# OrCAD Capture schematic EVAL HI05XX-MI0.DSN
size A; title: EVAL HI05XX-MI0; rev: A0; note: 1
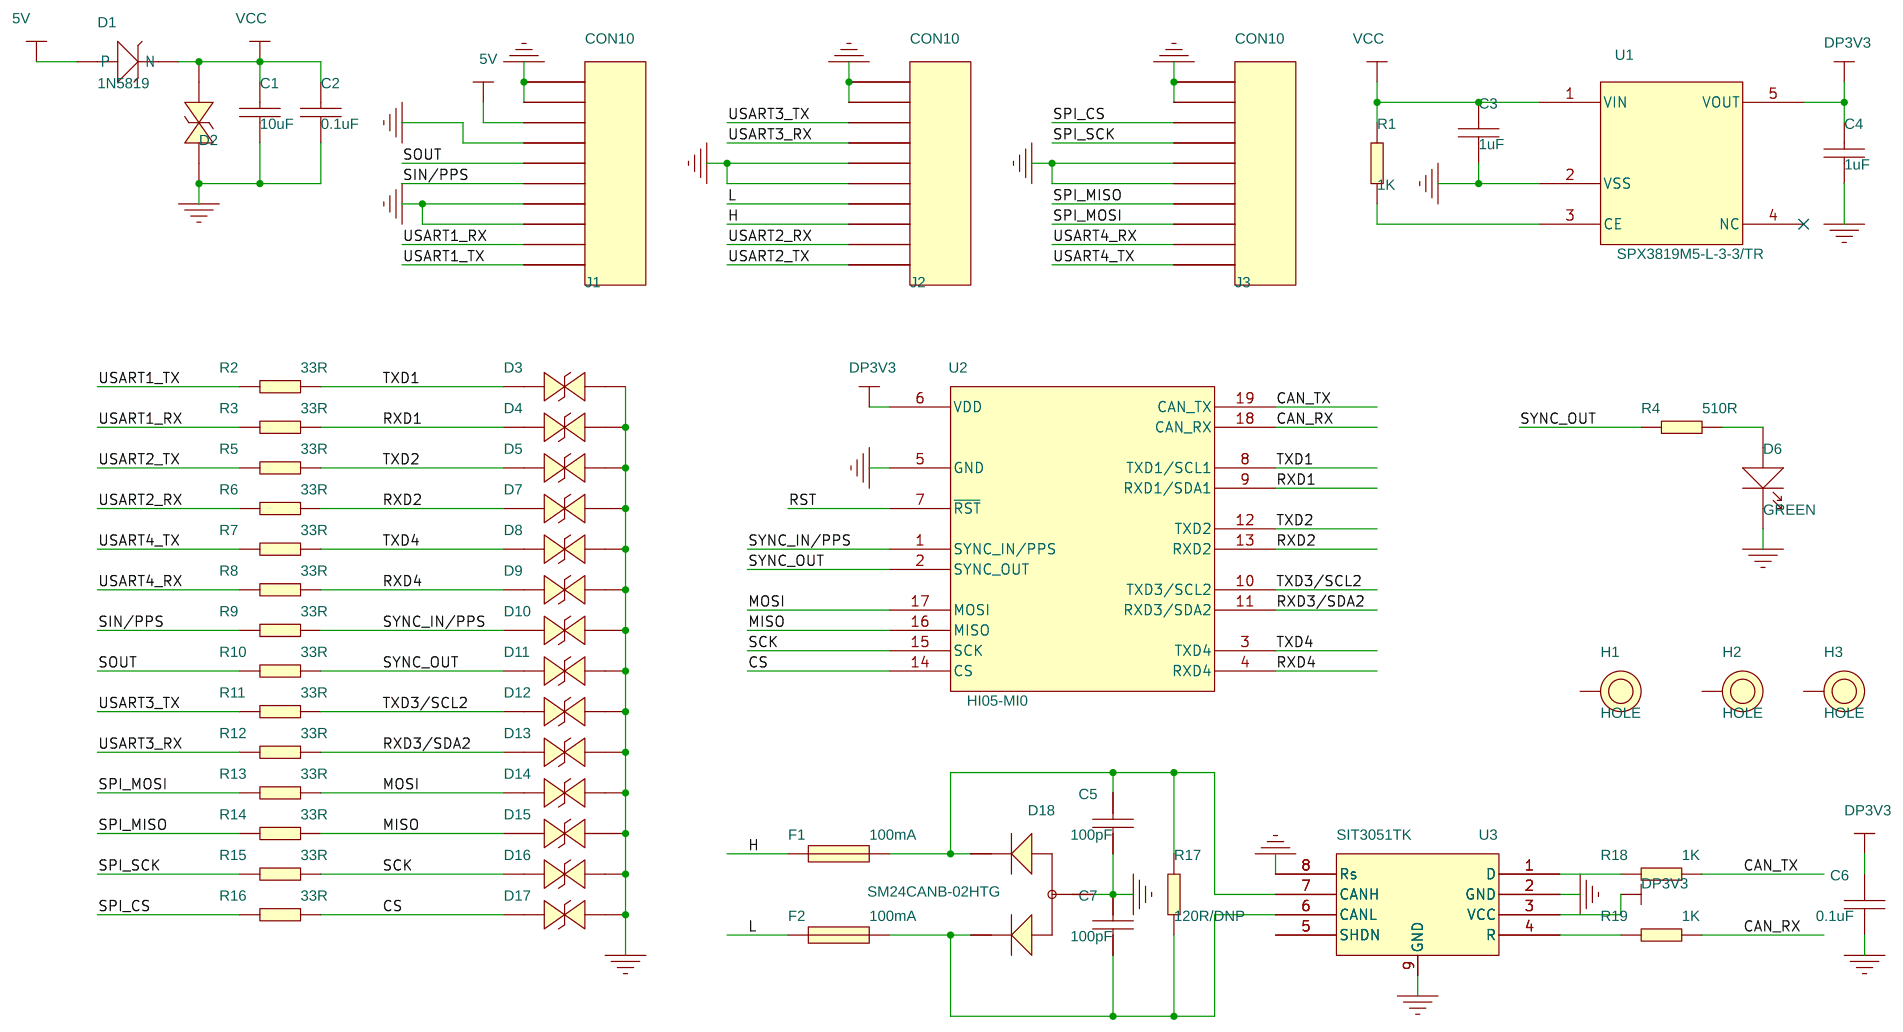
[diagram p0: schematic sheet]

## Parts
C1  10uF  [C0603]
C2  0.1uF  [C0402]
C3  1uF  [C0402]
C4  1uF  [C0402]
C5  100pF  [C0402]
C6  0.1uF  [C0402]
C7  100pF  [C0402]
D1  1N5819  [SOD123FL]
D2  SDD32A05L01  [SOD123FL]
D3  SBD52C05L01  [SOD-523]
D4  SBD52C05L01  [SOD-523]
D5  SBD52C05L01  [SOD-523]
D6  GREEN  [LED0402]
D7  SBD52C05L01  [SOD-523]
D8  SBD52C05L01  [SOD-523]
D9  SBD52C05L01  [SOD-523]
D10  SBD52C05L01  [SOD-523]
D11  SBD52C05L01  [SOD-523]
D12  SBD52C05L01  [SOD-523]
D13  SBD52C05L01  [SOD-523]
D14  SBD52C05L01  [SOD-523]
D15  SBD52C05L01  [SOD-523]
D16  SBD52C05L01  [SOD-523]
D17  SBD52C05L01  [SOD-523]
D18  SM24CANB-02HTG  [SOT23-3-0_95]
F1  100mA  [F0603]
F2  100mA  [F0603]
H1  HOLE  [HOLE-2-MM]
H2  HOLE  [HOLE-2-MM]
H3  HOLE  [HOLE-2-MM]
J1  CON10  [5015680807_1]
J2  CON10  [5015680807_1]
J3  CON10  [5015680807_1]
R1  1K  [R0402]
R2  33R  [R0402]
R3  33R  [R0402]
R4  510R  [R0402]
R5  33R  [R0402]
R6  33R  [R0402]
R7  33R  [R0402]
R8  33R  [R0402]
R9  33R  [R0402]
R10  33R  [R0402]
R11  33R  [R0402]
R12  33R  [R0402]
R13  33R  [R0402]
R14  33R  [R0402]
R15  33R  [R0402]
R16  33R  [R0402]
R17  120R/DNP  [R0805]
R18  1K  [R0402]
R19  1K  [R0402]
U1  SPX3819M5-L-3-3/TR  [SOT23-5-0_95]
U2  HI05-MI0  [HI05]
U3  SIT3051TK  [HVSON8]

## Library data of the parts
C1-C7 = Capacity_Nonpolarity
D1 = diode
D2-D5 D7-D17 = DIODE_BI-DIR_TRIG
D6 = LED
D18 = BAT54A_SOT
F1 F2 = Fuse
H1-H3 = HOLE
J1-J3 = CON10
R1-R19 = Res
U1 = XC6210
U2 = HI05-MI0
U3 = SIT3051TK

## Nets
5V: D1.1(P) J1.8
GND: C1.1 C2.1 C3.2 C4.1 C5.2 C6.2 C7.1 D2.1 D3.1 D4.1 D5.1 D6.2(-) D7.1 D8.1 D9.1 D10.1 D11.1 D12.1 D13.1 D14.1 D15.1 D16.1 D17.1 D18.3 J1.3 J1.4 J1.7 J1.9 J1.10 J2.5 J2.6 J2.9 J2.10 J3.5 J3.6 J3.9 J3.10 U1.2(VSS) U2.5(GND) U3.2(GND) U3.8(Rs) U3.9(GND)
VCC: C1.2 C2.2 C3.1 D1.2(N) D2.2 R1.2 U1.1(VIN)
CAN_RX: R19.1 U2.18(CAN_RX)
CAN_TX: R18.1 U2.19(CAN_TX)
CS: D17.2 R16.1 U2.14(CS)
DP3V3: C4.2 C6.1 U1.5(VOUT) U2.6(VDD) U3.3(VCC)
H: F1.1 J2.3
L: F2.1 J2.4
MISO: D15.2 R14.1 U2.16(MISO)
MOSI: D14.2 R13.1 U2.17(MOSI)
RST: U2.7(~{RST})
RXD1: D4.2 R3.1 U2.9(RXD1/SDA1)
RXD2: D7.2 R6.1 U2.13(RXD2)
RXD3/SDA2: D13.2 R12.1 U2.11(RXD3/SDA2)
RXD4: D9.2 R8.1 U2.4(RXD4)
SCK: D16.2 R15.1 U2.15(SCK)
SIN/PPS: J1.5 R9.2
SOUT: J1.6 R10.2
SPI_CS: J3.8 R16.2
SPI_MISO: J3.4 R14.2
SPI_MOSI: J3.3 R13.2
SPI_SCK: J3.7 R15.2
SYNC_IN/PPS: D10.2 R9.1 U2.1(SYNC_IN/PPS)
SYNC_OUT: D11.2 R4.1 R10.1 U2.2(SYNC_OUT)
TXD1: D3.2 R2.1 U2.8(TXD1/SCL1)
TXD2: D5.2 R5.1 U2.12(TXD2)
TXD3/SCL2: D12.2 R11.1 U2.10(TXD3/SCL2)
TXD4: D8.2 R7.1 U2.3(TXD4)
USART1_RX: J1.2 R3.2
USART1_TX: J1.1 R2.2
USART2_RX: J2.2 R6.2
USART2_TX: J2.1 R5.2
USART3_RX: J2.7 R12.2
USART3_TX: J2.8 R11.2
USART4_RX: J3.2 R8.2
USART4_TX: J3.1 R7.2
N2198535: D6.1(+) R4.2
N2215668: C5.1 D18.1 F1.2 R17.2 U3.7(CANH)
N2215720: R18.2 U3.1(D)
N2215758: C7.2 D18.2 F2.2 R17.1 U3.6(CANL)
N2215796: R19.2 U3.4(R)
N2224750: R1.1 U1.3(CE)

Not connected (* = marked no-connect by the designer): H1 1; H2 1; H3 1; U1 4(NC)*; U3 5(SHDN)
